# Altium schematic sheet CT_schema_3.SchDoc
size 289 x 159 mm
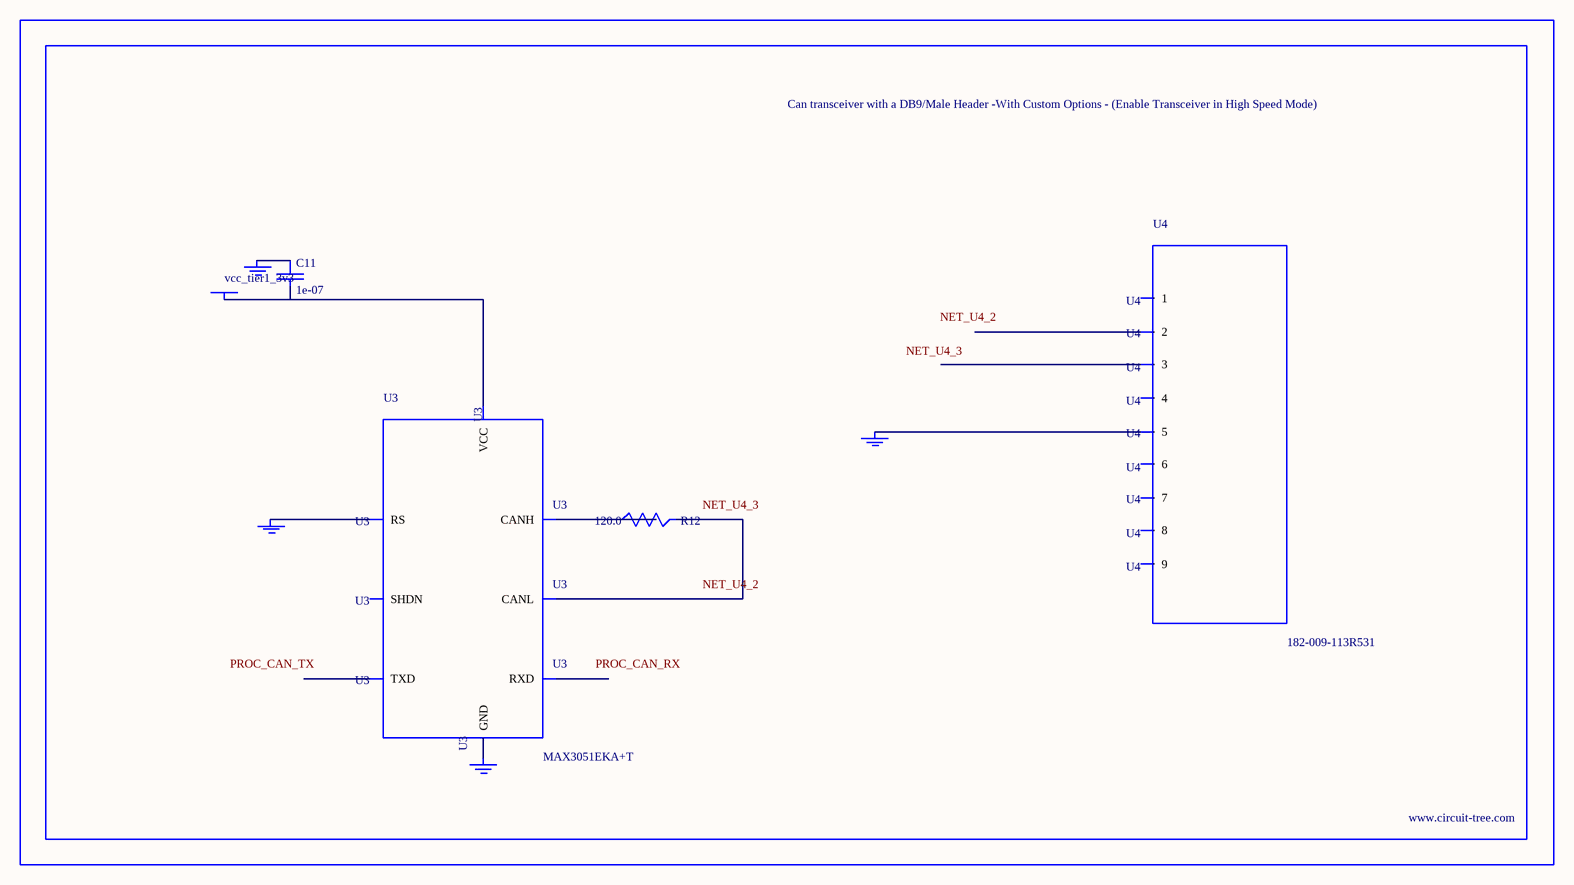
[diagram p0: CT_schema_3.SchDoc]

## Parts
BORDER2  (no value)
C11  1e-07  [C0402]
GND_INSTANCE_2_0  (no value)
GND_INSTANCE_2_1  (no value)
GND_INSTANCE_2_2  (no value)
GND_INSTANCE_2_3  (no value)
POWER_INSTANCE_2_0  vcc_tier1_3v3
R12  120.0  [R0603]
U3  MAX3051EKA+T  [SOT-23-8]
U4  182-009-113R531  [182-009-MALE]

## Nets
NetC11_1: C11.1 GND_INSTANCE_2_0.0(GND)
NetC11_2: C11.2 POWER_INSTANCE_2_0.0(PWR) U3.3(VCC)
NetGND_INSTANCE_2_1_0: GND_INSTANCE_2_1.0(GND) U3.8(RS)
NetGND_INSTANCE_2_2_0: GND_INSTANCE_2_2.0(GND) U3.2(GND)
NetGND_INSTANCE_2_3_0: GND_INSTANCE_2_3.0(GND) U4.5
NetR12_1: R12.1 U3.7(CANH)
NetR12_2: R12.2 U3.6(CANL)

Not connected (* = marked no-connect by the designer): U3 1(TXD) 4(RXD) 5(SHDN); U4 1 2 3 4 6 7 8 9

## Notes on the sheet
- Labels drawn without touching a wire or pin: NET_U4_2, NET_U4_3, PROC_CAN_RX, PROC_CAN_TX

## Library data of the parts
BORDER2 = BORDER_PAGE2
C11 = C0402C104K3RACTU
GND_INSTANCE_2_0-GND_INSTANCE_2_3 = GND
POWER_INSTANCE_2_0 = PWR
R12 = RC0603JR-07120RL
